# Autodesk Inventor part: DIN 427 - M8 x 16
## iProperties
Created: 2006-02
Part Number: DIN 427 - M8 x 16
Material: Steel, Mild
Description: Slotted Drilled Fillister Head Machine Screw
Document SubType Name: Modeling
Standard: DIN 427
Designer: Andy Moles
Standards Organization: DIN
Language: en-US
Size Designation: M8 x 16
Categories: <MemberInstance><Categories><Category DisplayName="Fasteners" InternalName="e4da775c-781d-43d5-af7c-5136215cf5a6" Mnemonic="FSTN"><Category DisplayName="Bolts"
Density: 1 g/cm^3
Author: Andy Moles
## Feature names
1. Body [Revolution]
2. Chamfer1
3. Slot [Extrusion]
4. Chamfer2
5. Chamfer3
